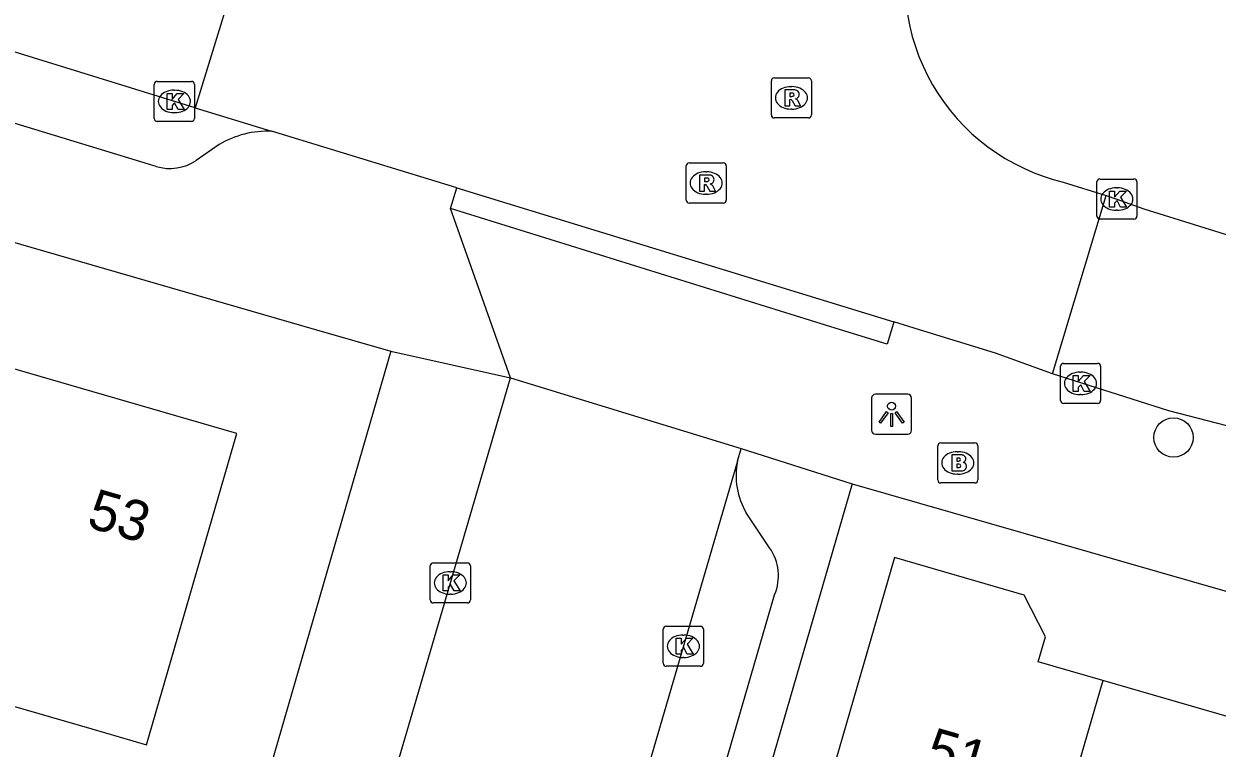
# Model space of a CAD drawing. Extents: x 159718 to 160783, y 383290 to 384030.
# Drawn here: x 159998.31 to 160028.05, y 383489.56 to 383507.63 of the extents above; entities that cross this region are included whole.
import ezdxf

# ---------------------------------------------------------------- set-up
doc = ezdxf.new("R2010")
doc.units = 0
for name, color, linetype in [('IMGEO_Boom', 7, 'Continuous'), ('IMGEO_Brandkraan', 7, 'Continuous'), ('IMGEO_Kolk', 7, 'Continuous'), ('IMGEO_Lichtpunt', 7, 'Continuous'), ('IMGEO_Pand', 7, 'Continuous'), ('IMGEO_Pand_nummerreeks', 7, 'Continuous'), ('IMGEO_Rijbaan_lokaal_open', 7, 'Continuous'), ('IMGEO_Rioolput', 7, 'Continuous'), ('IMGEO_Voetpad_open', 7, 'Continuous')]:
    doc.layers.add(name, color=color, linetype=linetype)

msp = doc.modelspace()

# ---------------------------------------------------------------- linework, layer by layer
at = {"layer": 'IMGEO_Boom'}
msp.add_circle((160026.964, 383497.313), 0.489, dxfattribs=at)
at = {"layer": 'IMGEO_Brandkraan'}
for p, q in [((160021.088, 383496.253), (160021.088, 383497.105)), ((160021.163, 383497.179), (160022.015, 383497.179)), ((160021.576, 383496.959), (160021.601, 383496.959)), ((160022.089, 383497.105), (160022.089, 383496.253)), ((160021.599, 383496.399), (160021.574, 383496.399)), ((160022.015, 383496.179), (160021.163, 383496.179))]:
    msp.add_line(p, q, dxfattribs=at)
for points in [[(160021.088, 383496.253), (160021.088, 383497.105)], [(160021.163, 383497.179), (160022.015, 383497.179)], [(160022.089, 383497.105), (160022.089, 383496.253)], [(160021.436, 383496.879), (160021.436, 383496.479), (160021.649, 383496.479)], [(160021.667, 383496.879), (160021.436, 383496.879)], [(160021.615, 383496.798), (160021.561, 383496.798), (160021.561, 383496.722)], [(160021.561, 383496.722), (160021.614, 383496.722)], [(160021.623, 383496.646), (160021.561, 383496.646), (160021.561, 383496.565)], [(160021.561, 383496.565), (160021.623, 383496.565)], [(160022.015, 383496.179), (160021.163, 383496.179)]]:
    msp.add_lwpolyline(points, dxfattribs=at)
for centre, radius, start, end in [((160021.165, 383497.103), 0.0765, 91.552, 178.448), ((160021.165, 383497.103), 0.0765, 91.552, 178.448), ((160022.013, 383497.103), 0.0765, 1.552, 88.448), ((160022.013, 383497.103), 0.0765, 1.552, 88.448), ((160021.616, 383496.76), 0.0379, 267.8285, 90.9355), ((160021.671, 383496.734), 0.145, 59.4692, 91.5367), ((160021.696, 383496.781), 0.0922, 285.5137, 58.1501), ((160021.701, 383496.589), 0.105, 301.3115, 78.989), ((160021.624, 383496.605), 0.0404, 269.8759, 90.5077), ((160021.655, 383496.73), 0.251, 268.6676, 293.5347), ((160021.165, 383496.255), 0.0765, 181.552, 268.448), ((160021.165, 383496.255), 0.0765, 181.552, 268.448), ((160022.013, 383496.255), 0.0765, 271.552, 358.448), ((160022.013, 383496.255), 0.0765, 271.552, 358.448)]:
    msp.add_arc(centre, radius, start, end, dxfattribs=at)
for centre, major_axis, ratio, start_param, end_param in [((160021.575, 383496.679), (-0.387, 0.002), 0.722429, 4.712389, 7.853982), ((160021.6, 383496.679), (-0.39, 0.002), 0.717154, 1.570796, 4.712389)]:
    msp.add_ellipse(centre, major_axis=major_axis, ratio=ratio, start_param=start_param, end_param=end_param, dxfattribs=at)
at = {"layer": 'IMGEO_Kolk'}
for p, q in [((160001.633, 383506.196), (160002.485, 383506.196)), ((160001.558, 383505.27), (160001.558, 383506.122)), ((160002.046, 383505.976), (160002.071, 383505.976)), ((160002.559, 383506.122), (160002.559, 383505.27)), ((160002.069, 383505.416), (160002.044, 383505.416)), ((160002.485, 383505.196), (160001.633, 383505.196)), ((160025.052, 383502.835), (160025.052, 383503.687)), ((160025.127, 383503.761), (160025.979, 383503.761)), ((160025.54, 383503.541), (160025.565, 383503.541)), ((160026.053, 383503.687), (160026.053, 383502.835)), ((160025.563, 383502.981), (160025.538, 383502.981)), ((160025.979, 383502.761), (160025.127, 383502.761)), ((160024.146, 383498.236), (160024.146, 383499.088)), ((160024.221, 383499.162), (160025.073, 383499.162)), ((160025.147, 383499.088), (160025.147, 383498.236)), ((160024.634, 383498.942), (160024.659, 383498.942)), ((160025.073, 383498.162), (160024.221, 383498.162)), ((160024.657, 383498.382), (160024.632, 383498.382)), ((160008.437, 383493.259), (160008.437, 383494.111)), ((160008.512, 383494.185), (160009.364, 383494.185)), ((160009.438, 383494.111), (160009.438, 383493.259)), ((160008.925, 383493.965), (160008.95, 383493.965)), ((160008.948, 383493.405), (160008.923, 383493.405)), ((160009.364, 383493.185), (160008.512, 383493.185)), ((160014.247, 383491.679), (160014.247, 383492.531)), ((160014.322, 383492.605), (160015.174, 383492.605)), ((160015.248, 383492.531), (160015.248, 383491.679)), ((160014.735, 383492.385), (160014.76, 383492.385)), ((160015.174, 383491.605), (160014.322, 383491.605)), ((160014.758, 383491.825), (160014.733, 383491.825))]:
    msp.add_line(p, q, dxfattribs=at)
for points in [[(160001.633, 383506.196), (160002.485, 383506.196)], [(160001.558, 383505.27), (160001.558, 383506.122)], [(160001.879, 383505.896), (160002.002, 383505.896), (160002.002, 383505.745), (160002.132, 383505.896), (160002.296, 383505.896), (160002.15, 383505.745), (160002.303, 383505.496), (160002.151, 383505.496), (160002.066, 383505.66), (160002.002, 383505.593), (160002.002, 383505.496), (160001.879, 383505.496), (160001.879, 383505.896)], [(160002.559, 383506.122), (160002.559, 383505.27)], [(160002.485, 383505.196), (160001.633, 383505.196)], [(160025.052, 383502.835), (160025.052, 383503.687)], [(160025.127, 383503.761), (160025.979, 383503.761)], [(160026.053, 383503.687), (160026.053, 383502.835)], [(160025.373, 383503.461), (160025.496, 383503.461), (160025.496, 383503.31), (160025.626, 383503.461), (160025.79, 383503.461), (160025.644, 383503.31), (160025.797, 383503.061), (160025.645, 383503.061), (160025.56, 383503.225), (160025.496, 383503.158), (160025.496, 383503.061), (160025.373, 383503.061), (160025.373, 383503.461)], [(160025.979, 383502.761), (160025.127, 383502.761)], [(160024.146, 383498.236), (160024.146, 383499.088)], [(160024.221, 383499.162), (160025.073, 383499.162)], [(160025.147, 383499.088), (160025.147, 383498.236)], [(160024.467, 383498.862), (160024.59, 383498.862), (160024.59, 383498.711), (160024.72, 383498.862), (160024.884, 383498.862), (160024.738, 383498.711), (160024.891, 383498.462), (160024.739, 383498.462), (160024.654, 383498.626), (160024.59, 383498.559), (160024.59, 383498.462), (160024.467, 383498.462), (160024.467, 383498.862)], [(160025.073, 383498.162), (160024.221, 383498.162)], [(160008.437, 383493.259), (160008.437, 383494.111)], [(160008.512, 383494.185), (160009.364, 383494.185)], [(160009.438, 383494.111), (160009.438, 383493.259)], [(160008.758, 383493.885), (160008.881, 383493.885), (160008.881, 383493.734), (160009.011, 383493.885), (160009.175, 383493.885), (160009.029, 383493.734), (160009.182, 383493.485), (160009.03, 383493.485), (160008.945, 383493.649), (160008.881, 383493.582), (160008.881, 383493.485), (160008.758, 383493.485), (160008.758, 383493.885)], [(160009.364, 383493.185), (160008.512, 383493.185)], [(160014.247, 383491.679), (160014.247, 383492.531)], [(160014.322, 383492.605), (160015.174, 383492.605)], [(160015.248, 383492.531), (160015.248, 383491.679)], [(160014.568, 383492.305), (160014.691, 383492.305), (160014.691, 383492.154), (160014.821, 383492.305), (160014.985, 383492.305), (160014.839, 383492.154), (160014.992, 383491.905), (160014.84, 383491.905), (160014.755, 383492.069), (160014.691, 383492.002), (160014.691, 383491.905), (160014.568, 383491.905), (160014.568, 383492.305)], [(160015.174, 383491.605), (160014.322, 383491.605)]]:
    msp.add_lwpolyline(points, dxfattribs=at)
for centre, start, end in [((160001.635, 383506.12), 91.552, 178.448), ((160001.635, 383506.12), 91.552, 178.448), ((160002.483, 383506.12), 1.552, 88.448), ((160002.483, 383506.12), 1.552, 88.448), ((160001.635, 383505.272), 181.552, 268.448), ((160001.635, 383505.272), 181.552, 268.448), ((160002.483, 383505.272), 271.552, 358.448), ((160002.483, 383505.272), 271.552, 358.448), ((160025.129, 383503.685), 91.552, 178.448), ((160025.129, 383503.685), 91.552, 178.448), ((160025.977, 383503.685), 1.552, 88.448), ((160025.977, 383503.685), 1.552, 88.448), ((160025.129, 383502.837), 181.552, 268.448), ((160025.129, 383502.837), 181.552, 268.448), ((160025.977, 383502.837), 271.552, 358.448), ((160025.977, 383502.837), 271.552, 358.448), ((160024.223, 383499.086), 91.552, 178.448), ((160024.223, 383499.086), 91.552, 178.448), ((160025.071, 383499.086), 1.552, 88.448), ((160025.071, 383499.086), 1.552, 88.448), ((160024.223, 383498.238), 181.552, 268.448), ((160024.223, 383498.238), 181.552, 268.448), ((160025.071, 383498.238), 271.552, 358.448), ((160025.071, 383498.238), 271.552, 358.448), ((160008.514, 383494.109), 91.552, 178.448), ((160008.514, 383494.109), 91.552, 178.448), ((160009.362, 383494.109), 1.552, 88.448), ((160009.362, 383494.109), 1.552, 88.448), ((160008.514, 383493.261), 181.552, 268.448), ((160008.514, 383493.261), 181.552, 268.448), ((160009.362, 383493.261), 271.552, 358.448), ((160009.362, 383493.261), 271.552, 358.448), ((160014.324, 383492.529), 91.552, 178.448), ((160014.324, 383492.529), 91.552, 178.448), ((160015.172, 383492.529), 1.552, 88.448), ((160015.172, 383492.529), 1.552, 88.448), ((160014.324, 383491.681), 181.552, 268.448), ((160014.324, 383491.681), 181.552, 268.448), ((160015.172, 383491.681), 271.552, 358.448), ((160015.172, 383491.681), 271.552, 358.448)]:
    msp.add_arc(centre, 0.0765, start, end, dxfattribs=at)
for centre, major_axis, ratio, start_param, end_param in [((160002.045, 383505.696), (-0.387, 0.002), 0.722429, 4.712389, 7.853982), ((160002.07, 383505.696), (-0.39, 0.002), 0.717154, 1.570796, 4.712389), ((160025.539, 383503.261), (-0.387, 0.002), 0.722429, 4.712389, 7.853982), ((160025.564, 383503.261), (-0.39, 0.002), 0.717154, 1.570796, 4.712389), ((160024.633, 383498.662), (-0.387, 0.002), 0.722429, 4.712389, 7.853982), ((160024.658, 383498.662), (-0.39, 0.002), 0.717154, 1.570796, 4.712389), ((160008.924, 383493.685), (-0.387, 0.002), 0.722429, 4.712389, 7.853982), ((160008.949, 383493.685), (-0.39, 0.002), 0.717154, 1.570796, 4.712389), ((160014.734, 383492.105), (-0.387, 0.002), 0.722429, 4.712389, 7.853982), ((160014.759, 383492.105), (-0.39, 0.002), 0.717154, 1.570796, 4.712389)]:
    msp.add_ellipse(centre, major_axis=major_axis, ratio=ratio, start_param=start_param, end_param=end_param, dxfattribs=at)
at = {"layer": 'IMGEO_Lichtpunt'}
for p, q in [((160019.439, 383498.296), (160019.439, 383497.489)), ((160019.439, 383498.296), (160019.439, 383497.489)), ((160020.341, 383498.391), (160019.533, 383498.391)), ((160020.341, 383498.391), (160019.533, 383498.391)), ((160020.435, 383497.489), (160020.435, 383498.296)), ((160020.435, 383497.489), (160020.435, 383498.296)), ((160019.533, 383497.395), (160020.341, 383497.395)), ((160019.533, 383497.395), (160020.341, 383497.395))]:
    msp.add_line(p, q, dxfattribs=at)
for points in [[(160019.813, 383497.96), (160019.852, 383497.932), (160019.664, 383497.67), (160019.626, 383497.697), (160019.813, 383497.96)], [(160019.915, 383497.912), (160019.962, 383497.912), (160019.962, 383497.59), (160019.915, 383497.59), (160019.915, 383497.912)], [(160020.025, 383497.932), (160020.063, 383497.959), (160020.25, 383497.697), (160020.211, 383497.669), (160020.025, 383497.932)]]:
    msp.add_lwpolyline(points, dxfattribs=at)
msp.add_circle((160019.938, 383498.094), 0.0994, dxfattribs=at)
for centre, start, end in [((160019.533, 383498.296), 90, 180), ((160019.533, 383498.296), 90, 180), ((160020.341, 383498.296), 0, 90), ((160020.341, 383498.296), 0, 90), ((160019.533, 383497.489), 180, 270), ((160019.533, 383497.489), 180, 270), ((160020.341, 383497.489), 270, 0), ((160020.341, 383497.489), 270, 360)]:
    msp.add_arc(centre, 0.0946, start, end, dxfattribs=at)
at = {"layer": 'IMGEO_Pand'}
for points in [[(159995.717, 383491.282), (160000, 383490.041), (160001.364, 383489.646), (160003.614, 383497.41), (160000, 383498.457), (159997.937, 383499.055)], [(160025.202, 383491.251), (160023.593, 383491.718), (160023.774, 383492.343), (160023.242, 383493.382), (160020.014, 383494.317), (160017.345, 383485.104), (160022.949, 383483.48)], [(160025.202, 383491.251), (160022.949, 383483.48)], [(160030.628, 383489.679), (160025.202, 383491.251)]]:
    msp.add_lwpolyline(points, dxfattribs=at)
at = {"layer": 'IMGEO_Rijbaan_lokaal_open'}
for points in [[(160002.575, 383505.538), (159955.256, 383520.188), (159948.518, 383522.212)], [(160003.952, 383510.001), (160002.575, 383505.538)], [(160002.575, 383505.538), (160004.483, 383504.953)], [(160009.098, 383503.537), (160004.861, 383504.837), (160004.483, 383504.953)], [(160009.098, 383503.537), (160019.997, 383500.196)], [(160024.218, 383503.68), (160025.287, 383503.349)], [(160023.952, 383498.899), (160025.287, 383503.349)], [(160025.287, 383503.349), (160025.553, 383503.261), (160025.764, 383503.184), (160026.229, 383503.016), (160030.39, 383501.718)], [(160023.952, 383498.899), (160022.529, 383499.419), (160020.634, 383500), (160019.997, 383500.196)], [(160005.308, 383481.268), (160010.436, 383498.802)], [(160010.436, 383498.802), (160016.186, 383497.035)], [(160029.484, 383497.298), (160026.851, 383497.979), (160023.952, 383498.899)], [(160016.093, 383496.718), (160016.186, 383497.035)], [(160016.093, 383496.718), (160010.885, 383478.881)]]:
    msp.add_lwpolyline(points, dxfattribs=at)
msp.add_arc((160025.427, 383508.699), 5.162, 163.7404, 256.459, dxfattribs=at)
at = {"layer": 'IMGEO_Rioolput'}
for p, q in [((160016.94, 383505.359), (160016.94, 383506.211)), ((160017.015, 383506.285), (160017.867, 383506.285)), ((160017.941, 383506.211), (160017.941, 383505.359)), ((160017.428, 383506.065), (160017.453, 383506.065)), ((160017.867, 383505.285), (160017.015, 383505.285)), ((160017.451, 383505.505), (160017.426, 383505.505)), ((160014.89, 383504.161), (160015.742, 383504.161)), ((160014.815, 383503.235), (160014.815, 383504.087)), ((160015.303, 383503.941), (160015.328, 383503.941)), ((160015.816, 383504.087), (160015.816, 383503.235)), ((160015.326, 383503.381), (160015.301, 383503.381)), ((160015.742, 383503.161), (160014.89, 383503.161))]:
    msp.add_line(p, q, dxfattribs=at)
for points in [[(160016.94, 383505.359), (160016.94, 383506.211)], [(160017.015, 383506.285), (160017.867, 383506.285)], [(160017.941, 383506.211), (160017.941, 383505.359)], [(160017.529, 383505.983), (160017.277, 383505.985), (160017.277, 383505.585)], [(160017.455, 383505.904), (160017.401, 383505.904), (160017.401, 383505.823)], [(160017.277, 383505.585), (160017.401, 383505.585), (160017.401, 383505.747), (160017.412, 383505.747)], [(160017.401, 383505.823), (160017.453, 383505.823)], [(160017.459, 383505.718), (160017.53, 383505.585), (160017.67, 383505.585), (160017.605, 383505.711)], [(160017.867, 383505.285), (160017.015, 383505.285)], [(160014.89, 383504.161), (160015.742, 383504.161)], [(160014.815, 383503.235), (160014.815, 383504.087)], [(160015.404, 383503.859), (160015.152, 383503.861), (160015.152, 383503.461)], [(160015.816, 383504.087), (160015.816, 383503.235)], [(160015.152, 383503.461), (160015.276, 383503.461), (160015.276, 383503.623), (160015.287, 383503.623)], [(160015.33, 383503.78), (160015.276, 383503.78), (160015.276, 383503.699)], [(160015.276, 383503.699), (160015.328, 383503.699)], [(160015.334, 383503.594), (160015.405, 383503.461), (160015.545, 383503.461), (160015.48, 383503.587)], [(160015.742, 383503.161), (160014.89, 383503.161)]]:
    msp.add_lwpolyline(points, dxfattribs=at)
for centre, radius, start, end in [((160017.017, 383506.209), 0.0765, 91.552, 178.448), ((160017.017, 383506.209), 0.0765, 91.552, 178.448), ((160017.865, 383506.209), 0.0765, 1.552, 88.448), ((160017.865, 383506.209), 0.0765, 1.552, 88.448), ((160017.461, 383505.808), 0.0964, 77.0061, 93.1865), ((160017.475, 383505.865), 0.0378, 276.6634, 79.6772), ((160017.528, 383505.873), 0.109, 350.3612, 89.416), ((160017.411, 383505.694), 0.0533, 26.0293, 88.6989), ((160017.437, 383506.012), 0.19, 274.7715, 282.9687), ((160017.526, 383505.873), 0.112, 277.5842, 350.9817), ((160017.51, 383505.658), 0.108, 29.5134, 73.7905), ((160017.017, 383505.361), 0.0765, 181.552, 268.448), ((160017.017, 383505.361), 0.0765, 181.552, 268.448), ((160017.865, 383505.361), 0.0765, 271.552, 358.448), ((160017.865, 383505.361), 0.0765, 271.552, 358.448), ((160014.892, 383504.085), 0.0765, 91.552, 178.448), ((160014.892, 383504.085), 0.0765, 91.552, 178.448), ((160015.74, 383504.085), 0.0765, 1.552, 88.448), ((160015.74, 383504.085), 0.0765, 1.552, 88.448), ((160015.403, 383503.749), 0.109, 350.3612, 89.416), ((160015.286, 383503.57), 0.0533, 26.0293, 88.6989), ((160015.312, 383503.888), 0.19, 274.7715, 282.9687), ((160015.336, 383503.684), 0.0964, 77.0061, 93.1865), ((160015.35, 383503.741), 0.0378, 276.6634, 79.6772), ((160015.401, 383503.749), 0.112, 277.5842, 350.9817), ((160015.385, 383503.534), 0.108, 29.5134, 73.7905), ((160014.892, 383503.237), 0.0765, 181.552, 268.448), ((160014.892, 383503.237), 0.0765, 181.552, 268.448), ((160015.74, 383503.237), 0.0765, 271.552, 358.448), ((160015.74, 383503.237), 0.0765, 271.552, 358.448)]:
    msp.add_arc(centre, radius, start, end, dxfattribs=at)
for centre, major_axis, ratio, start_param, end_param in [((160017.427, 383505.785), (-0.387, 0.002), 0.722429, 4.712389, 7.853982), ((160017.452, 383505.785), (-0.39, 0.002), 0.717154, 1.570796, 4.712389), ((160015.302, 383503.661), (-0.387, 0.002), 0.722429, 4.712389, 7.853982), ((160015.327, 383503.661), (-0.39, 0.002), 0.717154, 1.570796, 4.712389)]:
    msp.add_ellipse(centre, major_axis=major_axis, ratio=ratio, start_param=start_param, end_param=end_param, dxfattribs=at)
at = {"layer": 'IMGEO_Voetpad_open'}
for points in [[(160001.606, 383504.075), (159950.562, 383519.658)], [(159980.836, 383507.178), (160000, 383501.624), (160005.602, 383500), (160007.454, 383499.463)], [(160003.176, 383504.62), (160002.599, 383504.219)], [(160008.939, 383503.025), (160009.098, 383503.537)], [(160010.436, 383498.802), (160008.939, 383503.025)], [(160019.997, 383500.196), (160019.937, 383500), (160019.825, 383499.64), (160018.667, 383500), (160008.939, 383503.025)], [(160007.454, 383499.463), (160001.455, 383478.735), (160000.503, 383479.04), (160000.429, 383478.787)], [(160007.454, 383499.463), (160010.436, 383498.802)], [(160016.186, 383497.035), (160018.953, 383496.159)], [(160018.953, 383496.159), (160012.776, 383474.819)], [(160018.953, 383496.159), (160052.755, 383486.447)], [(160016.897, 383494.559), (160016.314, 383495.435)], [(160013.474, 383481.167), (160017.022, 383493.39)]]:
    msp.add_lwpolyline(points, dxfattribs=at)
for centre, radius, start, end in [((160004.391, 383502.583), 2.372, 87.7745, 120.8131), ((160001.949, 383505.202), 1.178, 253.0541, 303.4484), ((160017.895, 383496.368), 1.836, 169.0069, 210.54), ((160015.908, 383493.862), 1.21, 337.0354, 35.1713)]:
    msp.add_arc(centre, radius, start, end, dxfattribs=at)

# ---------------------------------------------------------------- texts
at = {"layer": 'IMGEO_Pand_nummerreeks'}
for s, rotation, p in [('53', 343.8306, (159999.841, 383495.089)), ('51', 343.8355, (160020.734, 383489.131))]:
    msp.add_text(s, height=1, rotation=rotation, dxfattribs=at).set_placement(p)

doc.saveas('drawing.dxf')
